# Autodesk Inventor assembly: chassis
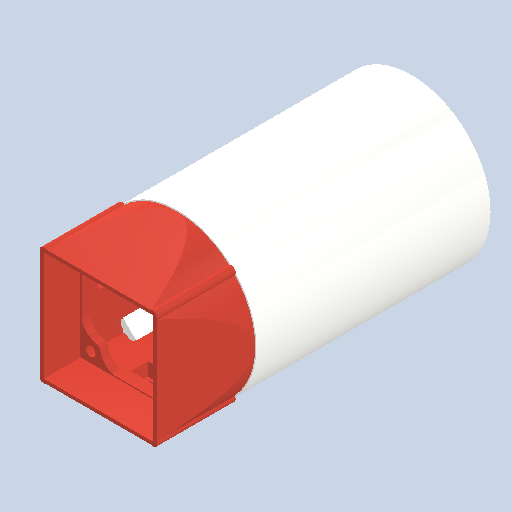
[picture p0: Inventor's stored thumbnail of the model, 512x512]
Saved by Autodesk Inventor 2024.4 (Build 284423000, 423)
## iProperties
Created: 2025-08
Part Number: chassis
Document SubType Name: Assembly
Designer: AdminForWorker
Title: chassis v9
Author: AdminForWorker
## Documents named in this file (6)
- c:\worker\convert-fusion-r04-cosv3\tmp\job-1\67\temp\files\d10a770d-4251-4a79-b0fc-d559600281fa\ec91a0e9-6193-47d4-9fc4-53f0dd8fc452.iam
- c:\worker\convert-fusion-r04-cosv3\tmp\job-1\67\temp\files\d10a770d-4251-4a79-b0fc-d559600281fa\Chassis.ipt
- c:\worker\convert-fusion-r04-cosv3\tmp\job-1\67\temp\files\d10a770d-4251-4a79-b0fc-d559600281fa\Battery.ipt
- c:\worker\convert-fusion-r04-cosv3\tmp\job-1\67\temp\files\d10a770d-4251-4a79-b0fc-d559600281fa\Clear pipe.ipt
- c:\worker\convert-fusion-r04-cosv3\tmp\job-1\67\temp\files\d10a770d-4251-4a79-b0fc-d559600281fa\RC receiever.ipt
- c:\worker\convert-fusion-r04-cosv3\tmp\job-1\67\temp\files\d10a770d-4251-4a79-b0fc-d559600281fa\M3 Nut v1.ipt
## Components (6 placed, 5 different names)
1. Chassis:1
2. Battery:1
3. Clear pipe:1
4. RC receiever:1
5. M3 Nut v1:1
6. M3 Nut v1:2
